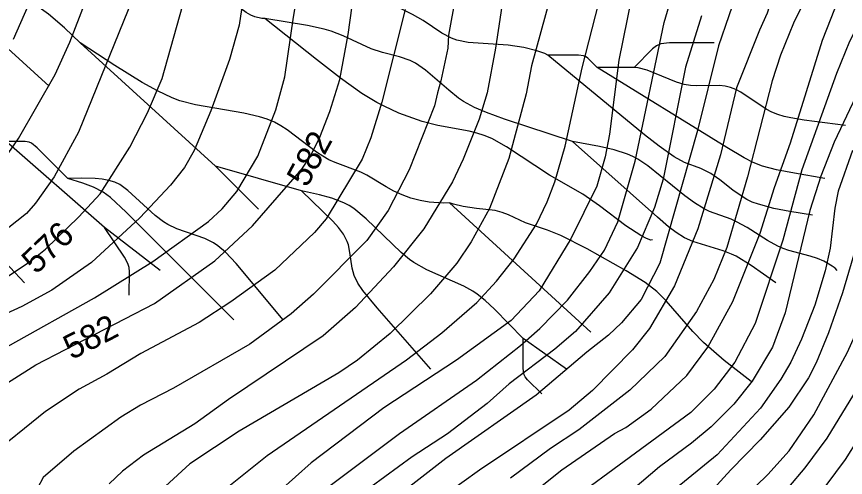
# Model space of a CAD drawing. Extents: x -709584 to -702006, y -1161789 to -1157496.
# Drawn here: x -708712.7 to -708376.2, y -1160078.5 to -1159891.3 of the extents above; entities that cross this region are included whole.
import ezdxf

# ---------------------------------------------------------------- set-up
doc = ezdxf.new("R2010")
doc.units = 0
for name, color, linetype in [('120_vrstevnice hlavní', 7, 'Continuous'), ('121_vrstevnice hlavní_popis', 7, 'Continuous'), ('122_vrstevnice základní', 7, 'Continuous'), ('411_akumulovaný odtok', 7, 'Continuous')]:
    doc.layers.add(name, color=color, linetype=linetype)

msp = doc.modelspace()

# ---------------------------------------------------------------- linework, layer by layer
at = {"layer": '120_vrstevnice hlavní'}
for points in [[(-708305.17, -1159622.86), (-708310.23, -1159641.37), (-708312.11, -1159650.63), (-708314.72, -1159669.14), (-708317.03, -1159706.17), (-708317.9, -1159757.09), (-708321.37, -1159808), (-708323.54, -1159821.89), (-708331.06, -1159840.4), (-708354.49, -1159891.32), (-708372, -1159923.72), (-708380.68, -1159942.23), (-708386.17, -1159956.12), (-708390.66, -1159970), (-708400.64, -1160011.66), (-708405.84, -1160025.55), (-708414.09, -1160039.43), (-708421.46, -1160048.69), (-708430.72, -1160057.95), (-708438.68, -1160064.6), (-708451.7, -1160074.15), (-708470.93, -1160090.64)], [(-708633.37, -1159627.34), (-708641.04, -1159641.37), (-708644.65, -1159650.05), (-708649.43, -1159676.09), (-708650.29, -1159684.77), (-708650.58, -1159697.78), (-708648.85, -1159734.52), (-708649.28, -1159755.35), (-708653.04, -1159775.89), (-708657.67, -1159792.09), (-708665.62, -1159808.29), (-708674.88, -1159824.49), (-708692.24, -1159852.84), (-708704.68, -1159878.88), (-708714.08, -1159900.57)], [(-708789.58, -1160084.27), (-708792.86, -1160072.53), (-708792.61, -1160069.11), (-708790.09, -1160064.95), (-708785.55, -1160060.3), (-708777.48, -1160053.94), (-708769.62, -1160049.56), (-708716.4, -1160025.26), (-708681.1, -1160005.59), (-708657.38, -1159990.83), (-708634.82, -1159974.49), (-708629.32, -1159969.43), (-708623.24, -1159962.34), (-708614.71, -1159948.02), (-708607.48, -1159929.21), (-708603.86, -1159915.76), (-708600.33, -1159891.54), (-708591.57, -1159840.69)], [(-708494.22, -1159876.56), (-708503.62, -1159911.28), (-708505.79, -1159922.71), (-708512.85, -1159948.88), (-708520.67, -1159969.19), (-708528.21, -1159982.73), (-708534, -1159991.41), (-708544.7, -1160003.85), (-708561.05, -1160020.05), (-708574.35, -1160030.9), (-708581.88, -1160035.96), (-708622.38, -1160059.68), (-708642.34, -1160072.99), (-708652.32, -1160082.1)], [(-708419.3, -1159878.59), (-708427.68, -1159903.18), (-708436.22, -1159937.6), (-708451.55, -1159991.41), (-708459.07, -1160006.17), (-708467.17, -1160015.71), (-708472.38, -1160020.77), (-708481.2, -1160027.57), (-708501.77, -1160045.09), (-708538.48, -1160070.82), (-708559.17, -1160086.88)], [(-708360.43, -1160046.09), (-708376.34, -1160071.26), (-708396.3, -1160098.16)]]:
    msp.add_lwpolyline(points, dxfattribs=at)
at = {"layer": '122_vrstevnice základní'}
for points in [[(-708524.02, -1160101.49), (-708491.33, -1160075.45), (-708469.92, -1160060.7), (-708465.29, -1160058.24), (-708455.02, -1160050.72), (-708440.56, -1160037.12), (-708432.02, -1160025.55), (-708421.9, -1160007.03), (-708410.76, -1159979.26), (-708404.98, -1159960.75), (-708398.47, -1159942.52), (-708385.45, -1159900.86), (-708373.73, -1159870.78), (-708363.9, -1159852.26), (-708354.35, -1159829.12), (-708349.87, -1159812.92), (-708345.96, -1159782.83), (-708346.1, -1159755.06), (-708350.16, -1159704.15), (-708349.58, -1159685.63), (-708347.7, -1159671.75), (-708342.63, -1159646.58), (-708332.22, -1159607.24)], [(-708437.52, -1160106.26), (-708407.72, -1160077.33), (-708399.05, -1160067.64), (-708389.07, -1160053.03), (-708375.32, -1160027.57), (-708371.13, -1160018.31), (-708364.76, -1159999.8), (-708358.26, -1159972.03), (-708355.51, -1159964.8), (-708350.59, -1159954.53), (-708323.11, -1159912.15), (-708298.81, -1159877.43), (-708289.69, -1159861.23), (-708285.64, -1159849.66), (-708281.45, -1159831.15), (-708279.71, -1159817.26), (-708279.86, -1159801.06), (-708278.12, -1159775.6), (-708277.25, -1159752.46), (-708274.07, -1159713.11), (-708273.93, -1159683.03), (-708272.48, -1159656.99), (-708271.04, -1159647.74), (-708260.77, -1159608.39)], [(-708317.9, -1159614.47), (-708327.01, -1159650.92), (-708332.22, -1159676.95), (-708333.67, -1159697.78), (-708333.52, -1159716.01), (-708332.08, -1159752.46), (-708334.24, -1159801.93), (-708336.7, -1159816.39), (-708343.21, -1159839.53), (-708347.41, -1159851.11), (-708358.98, -1159872.8), (-708363.9, -1159883.22), (-708370.55, -1159893.63), (-708374.46, -1159901.44), (-708379.81, -1159914.46), (-708393.84, -1159953.51), (-708401.65, -1159982.15), (-708412.79, -1160016), (-708421.03, -1160031.62), (-708429.42, -1160042.61), (-708438.97, -1160052.16), (-708513.03, -1160106.55)], [(-708585.93, -1160082.25), (-708557.29, -1160060.7), (-708526.04, -1160039), (-708508.11, -1160024.97), (-708500.3, -1160018.03), (-708489.01, -1160006.45), (-708479.9, -1159994.88), (-708473.97, -1159986.2), (-708468.62, -1159974.63), (-708461.53, -1159950.04), (-708449.82, -1159893.63), (-708436.22, -1159847.34), (-708433.47, -1159835.77), (-708430.43, -1159814.95), (-708430.87, -1159796.43), (-708432.17, -1159775.6), (-708434.48, -1159754.77), (-708437.52, -1159736.26), (-708439.26, -1159699.23), (-708437.52, -1159685.34), (-708434.48, -1159673.77), (-708426.53, -1159653.23), (-708413.08, -1159623.15)], [(-708252.23, -1159627.49), (-708256.43, -1159639.64), (-708259.32, -1159650.05), (-708261.63, -1159667.41), (-708261.63, -1159712.54), (-708265.25, -1159769.24), (-708266.55, -1159817.26), (-708269.01, -1159834.62), (-708271.76, -1159846.19), (-708275.08, -1159856.31), (-708279.28, -1159865.86), (-708307.34, -1159915.91), (-708316.74, -1159930.95), (-708335.84, -1159959.01), (-708345.24, -1159975.5), (-708351.6, -1159991.12), (-708362.31, -1160024.1), (-708366.93, -1160035.09), (-708383.71, -1160062.58), (-708392.68, -1160074.58), (-708419.15, -1160105.97)], [(-708724.06, -1160001.82), (-708707.14, -1159990.69), (-708701.06, -1159985.77), (-708687.47, -1159972.61), (-708678.79, -1159963.35), (-708666.78, -1159944.26), (-708659.55, -1159930.37), (-708653.62, -1159916.49), (-708638, -1159860.94), (-708632.79, -1159844.74), (-708618.91, -1159810.03), (-708614.85, -1159798.46), (-708610.8, -1159784.57), (-708607.33, -1159766.05), (-708607.48, -1159726.71), (-708609.07, -1159712.83), (-708613.55, -1159687.37), (-708614.71, -1159673.48), (-708613.99, -1159664.23), (-708612.69, -1159657.28), (-708608.64, -1159648.03), (-708603.28, -1159641.08), (-708594.75, -1159633.13)], [(-708627.29, -1160082.54), (-708610.95, -1160069.66), (-708554.39, -1160030.75), (-708540.07, -1160019.76), (-708525.9, -1160007.47), (-708517.8, -1159998.79), (-708510.71, -1159989.68), (-708501.6, -1159975.65), (-708497.26, -1159966.53), (-708494.22, -1159958.43), (-708490.03, -1159943.97), (-708483.08, -1159912.15), (-708474.98, -1159880.32), (-708465.44, -1159835.48), (-708464.42, -1159817.26), (-708465.44, -1159799.03), (-708478.17, -1159732.21), (-708481.49, -1159708.05), (-708480.91, -1159696.05), (-708479.47, -1159689.1), (-708473.54, -1159672.9), (-708466.31, -1159659.31), (-708461.82, -1159652.36), (-708446.2, -1159633.27)], [(-708356.81, -1159637.9), (-708361.87, -1159658.73), (-708364.19, -1159676.95), (-708364.04, -1159708.2), (-708362.74, -1159721.22), (-708359.7, -1159768.08), (-708360.43, -1159784.86), (-708364.33, -1159808), (-708367.08, -1159819.57), (-708371.42, -1159834.04), (-708381.98, -1159862.68), (-708397.31, -1159893.92), (-708402.52, -1159906.94), (-708405.99, -1159917.35), (-708415.97, -1159956.41), (-708424.36, -1159985.05), (-708429.57, -1159998.06), (-708436.65, -1160011.08), (-708449.53, -1160029.31), (-708463.7, -1160043.05), (-708484.39, -1160059.11), (-708495.96, -1160066.77), (-708512.16, -1160078.78)], [(-708613.26, -1159638.91), (-708618.04, -1159645.86), (-708622.38, -1159654.39), (-708624.55, -1159660.47), (-708626.57, -1159668.56), (-708627.01, -1159676.67), (-708626.14, -1159690.84), (-708619.77, -1159733.36), (-708619.48, -1159747.54), (-708621.65, -1159769.82), (-708623.24, -1159779.94), (-708624.83, -1159786.02), (-708633.08, -1159808.29), (-708643.93, -1159832.3), (-708654.92, -1159859.5), (-708663.89, -1159879.75), (-708687.61, -1159938.18), (-708697.45, -1159956.41), (-708705.11, -1159967.11), (-708708.73, -1159971.3), (-708721.31, -1159981.14)], [(-708718.57, -1159950.48), (-708711.91, -1159940.79), (-708697.01, -1159914.75), (-708691.08, -1159901.73), (-708671.7, -1159851.4), (-708665.05, -1159837.51), (-708650, -1159813.21), (-708645.23, -1159801.06), (-708640.89, -1159787.17), (-708634.82, -1159762.87), (-708632.5, -1159745.52), (-708632.07, -1159734.38), (-708633.66, -1159714.27), (-708636.26, -1159693.44), (-708636.55, -1159679.56), (-708635.1, -1159666.25), (-708631.92, -1159652.36), (-708625.99, -1159638.48)], [(-708375.76, -1159788.04), (-708379.08, -1159808.87), (-708387.76, -1159841.27), (-708392.39, -1159852.84), (-708396.01, -1159859.78), (-708401.5, -1159873.67), (-708405.71, -1159882.42), (-708408.01, -1159889.87), (-708411.05, -1159896.81), (-708420.41, -1159920.28), (-708426.96, -1159947.44), (-708436.07, -1159977.53), (-708445.62, -1160000.67), (-708455.75, -1160018.03), (-708462.69, -1160026.7), (-708478.89, -1160043.19), (-708488.29, -1160051.15), (-708524.71, -1160075.55), (-708539.08, -1160085.83)], [(-708528.79, -1159851.97), (-708537.33, -1159898.84), (-708537.62, -1159904.05), (-708540.4, -1159917.42), (-708541.81, -1159922.27), (-708543.05, -1159927.58), (-708553.38, -1159953.51), (-708561.92, -1159970), (-708570.45, -1159982.3), (-708592.15, -1160004), (-708601.26, -1160012.09), (-708618.04, -1160024.39), (-708648.99, -1160042.18), (-708662.44, -1160049.12), (-708670.4, -1160054.04), (-708689.49, -1160067.78), (-708701.93, -1160078.49), (-708704.25, -1160082.83)], [(-708616.59, -1159855.45), (-708622.38, -1159894.79), (-708626.28, -1159908.68), (-708633.8, -1159929.5), (-708640.6, -1159945.7), (-708644.51, -1159952.65), (-708650.29, -1159959.73), (-708662.73, -1159973.04), (-708682.26, -1159991.12), (-708698.46, -1160002.4), (-708710.61, -1160009.06), (-708740.98, -1160022.94)], [(-708723.63, -1160044.5), (-708704.97, -1160032.78), (-708656.8, -1160007.9), (-708632.21, -1159990.54), (-708616.88, -1159976.22), (-708596.92, -1159953.23), (-708593.45, -1159948.02), (-708589.54, -1159940.21), (-708585.49, -1159929.79), (-708581.44, -1159916.78), (-708578.12, -1159898.55), (-708574.79, -1159875.12)], [(-708514.62, -1159879.75), (-708518.23, -1159904.05), (-708521.7, -1159922.27), (-708524.89, -1159932.98), (-708531.4, -1159949.18), (-708535.73, -1159958.43), (-708547.31, -1159977.53), (-708559.75, -1159993), (-708575.08, -1160009.49), (-708588.24, -1160020.92), (-708626.72, -1160046.81), (-708640.31, -1160056.79), (-708661.14, -1160069.52), (-708669.68, -1160076.03), (-708675.17, -1160081.09)], [(-708462.98, -1159883.51), (-708468.19, -1159908.96), (-708471.95, -1159939.05), (-708473.68, -1159948.31), (-708477.15, -1159960.17), (-708487.71, -1159981.57), (-708500.58, -1160002.69), (-708511.87, -1160014.7), (-708534.08, -1160030.87), (-708563.65, -1160050.28), (-708593.16, -1160072.56), (-708605.89, -1160083.98)], [(-708554.97, -1159888.42), (-708564.37, -1159926.03), (-708568.86, -1159940.5), (-708572.47, -1159949.18), (-708587.08, -1159973.48), (-708591.71, -1159978.97), (-708607.91, -1159994.3), (-708625.7, -1160007.18), (-708638.58, -1160015.57), (-708662.3, -1160028.15), (-708676.04, -1160036.54), (-708687.32, -1160042.61), (-708701.06, -1160051.73), (-708724.5, -1160070.68)], [(-708434.63, -1159891.03), (-708441.14, -1159911.86), (-708450.25, -1159957.28), (-708453.72, -1159968.85), (-708460.66, -1159985.05), (-708472.09, -1160003.56), (-708485.83, -1160019.18), (-708494.22, -1160026.42), (-708512.74, -1160040.45), (-708521.7, -1160048.54), (-708537.76, -1160060.84), (-708552.08, -1160070.1), (-708574.35, -1160086.44)], [(-708373.3, -1159945.7), (-708379.08, -1159962.19), (-708380.53, -1159969.14), (-708382.41, -1159985.34), (-708384.44, -1159994.59), (-708388.63, -1160008.48), (-708393.98, -1160022.36), (-708398.32, -1160031.62), (-708402.37, -1160038.56), (-708410.62, -1160050.43), (-708428.26, -1160069.37), (-708463.56, -1160098.16)], [(-708367.22, -1159969.14), (-708377.35, -1160003.56), (-708382.99, -1160019.76), (-708388.05, -1160031.91), (-708391.23, -1160037.99), (-708399.19, -1160049.99), (-708410.76, -1160063.3), (-708422.77, -1160075.45), (-708439.69, -1160093.96)]]:
    msp.add_lwpolyline(points, dxfattribs=at)
at = {"layer": '411_akumulovaný odtok'}
for p, q in [((-708631.99, -1159952), (-708686.99, -1159902)), ((-708461.99, -1159912), (-708476.99, -1159912)), ((-708676.99, -1159977), (-708716.99, -1159942)), ((-708596.99, -1159962), (-708631.99, -1159952)), ((-708614.49, -1159969.5), (-708631.99, -1159952)), ((-708479.49, -1160019.5), (-708536.99, -1159967)), ((-708654.49, -1159994.5), (-708676.99, -1159977)), ((-708489.49, -1160034.5), (-708506.99, -1160022))]:
    msp.add_line(p, q, dxfattribs=at)
for points in [[(-708686.99, -1159902), (-708693.27, -1159895.87), (-708699.81, -1159890.33), (-708703.52, -1159887.55), (-708711.06, -1159882.53), (-708720.77, -1159877.04), (-708761.43, -1159855.42), (-708767.53, -1159851.9), (-708773.43, -1159848.11), (-708778.93, -1159843.82), (-708784.04, -1159839.04), (-708791.34, -1159831.38), (-708805.6, -1159815.53), (-708811.58, -1159809.57), (-708814.93, -1159806.56), (-708818.34, -1159803.73), (-708821.69, -1159801.25), (-708824.84, -1159799.25), (-708827.66, -1159797.85), (-708829.83, -1159797.11), (-708831.34, -1159796.85), (-708831.99, -1159797)], [(-708611.99, -1159892), (-708613.22, -1159892.09), (-708615.93, -1159891.43), (-708617.59, -1159890.71), (-708619.55, -1159889.55), (-708621.53, -1159888.06), (-708631.02, -1159879.71), (-708634.58, -1159877.11), (-708640.28, -1159873.65), (-708646.7, -1159870.72), (-708662.71, -1159865.02), (-708667.19, -1159863.24), (-708671.49, -1159861.14), (-708673.52, -1159859.91), (-708677.39, -1159857.15), (-708682.98, -1159852.6), (-708711.99, -1159827)], [(-708699.49, -1159919.5), (-708737.8, -1159884.67), (-708743.95, -1159879.45), (-708748.17, -1159876.28), (-708750.34, -1159874.87), (-708754.71, -1159872.68), (-708761.15, -1159870.03), (-708764.99, -1159867.84), (-708772.58, -1159862.9), (-708774.84, -1159861.63), (-708779.56, -1159859.36), (-708789.76, -1159855.21), (-708811.99, -1159847)], [(-708496.99, -1159907), (-708498.2, -1159906.33), (-708501.54, -1159905.12), (-708506.7, -1159903.86), (-708513.06, -1159902.95), (-708529.34, -1159901.74), (-708533.96, -1159900.81), (-708536.15, -1159900.06), (-708540.04, -1159897.99), (-708547.59, -1159892.92), (-708551.91, -1159890.43), (-708558.69, -1159887.08), (-708567.97, -1159883), (-708575.02, -1159880.24), (-708579.78, -1159878.68), (-708584.58, -1159877.56), (-708594.13, -1159875.9), (-708596.51, -1159875.22), (-708599.11, -1159874.13), (-708601.83, -1159872.7), (-708607.3, -1159869.25), (-708612.15, -1159865.76), (-708616.99, -1159862)], [(-708486.99, -1159942), (-708514.61, -1159933.01), (-708521.99, -1159930.3), (-708526.75, -1159928.24), (-708531.26, -1159925.77), (-708533.32, -1159924.35), (-708537.25, -1159921.2), (-708546.76, -1159912.99), (-708550.75, -1159910.21), (-708552.86, -1159909.1), (-708557.25, -1159907.57), (-708564.13, -1159905.87), (-708568.73, -1159904.36), (-708580.07, -1159899.07), (-708584.94, -1159897.21), (-708587.82, -1159896.39), (-708594.64, -1159894.88), (-708611.99, -1159892)], [(-708454.49, -1159982), (-708455.23, -1159982.09), (-708456.97, -1159981.5), (-708459.3, -1159980.28), (-708465.34, -1159976.23), (-708475.99, -1159968.18), (-708482.78, -1159963.36), (-708496.29, -1159955.64), (-708513.78, -1159944.13), (-708519.76, -1159940.85), (-708522.87, -1159939.55), (-708525.89, -1159938.62), (-708528.99, -1159937.89), (-708541.71, -1159935.54), (-708548.09, -1159933.83), (-708557.46, -1159930.45), (-708563.52, -1159927.73), (-708566.47, -1159926.19), (-708572.48, -1159922.51), (-708581.15, -1159916.33), (-708590.91, -1159908.76), (-708611.99, -1159892)], [(-708536.99, -1159967), (-708539.36, -1159967.1), (-708545.17, -1159966.64), (-708548.81, -1159966.01), (-708552.65, -1159965.01), (-708556.14, -1159963.72), (-708559.5, -1159962.16), (-708562.66, -1159960.46), (-708570.48, -1159955.73), (-708572.98, -1159954.45), (-708583.36, -1159950.57), (-708585.89, -1159949.43), (-708588.44, -1159948), (-708590.9, -1159946.36), (-708602.91, -1159937.26), (-708605.43, -1159935.64), (-708608.04, -1159934.23), (-708610.98, -1159933.01), (-708614.04, -1159932.03), (-708620.4, -1159930.57), (-708640.04, -1159927.18), (-708646.41, -1159925.48), (-708649.5, -1159924.33), (-708655.48, -1159921.5), (-708661.68, -1159918.03), (-708672.83, -1159911.11), (-708686.99, -1159902)], [(-708429.49, -1159902), (-708447.66, -1159901.93), (-708451.15, -1159902.28), (-708452.94, -1159903.13), (-708454.52, -1159904.42), (-708461.99, -1159912)], [(-708476.99, -1159912), (-708480.8, -1159908.15), (-708481.76, -1159907.46), (-708482.5, -1159907.17), (-708484.62, -1159906.97), (-708496.99, -1159907)], [(-708389.49, -1159972), (-708398.79, -1159970.47), (-708405.25, -1159969.18), (-708411.44, -1159967.55), (-708414.03, -1159966.61), (-708416.23, -1159965.55), (-708418.16, -1159964.4), (-708421.84, -1159961.74), (-708427.2, -1159957.55), (-708430.89, -1159955.03), (-708434.94, -1159953.04), (-708441.47, -1159950.5), (-708445.7, -1159948.19), (-708451.78, -1159943.92), (-708457.73, -1159939.25), (-708496.99, -1159907)], [(-708709.49, -1159999.5), (-708767.85, -1159937.19), (-708774.11, -1159930.32), (-708777.38, -1159925.86), (-708778.87, -1159923.38), (-708780.14, -1159920.86), (-708781.08, -1159918.41), (-708781.62, -1159916.42), (-708782.06, -1159913.29), (-708781.99, -1159912)], [(-708384.49, -1159957), (-708396.8, -1159954.93), (-708404.13, -1159953.53), (-708409.89, -1159952), (-708413.6, -1159950.54), (-708417.23, -1159948.69), (-708424.32, -1159944.52), (-708476.99, -1159912)], [(-708376.1, -1159935.52), (-708392.89, -1159933.41), (-708398.36, -1159932.45), (-708401.03, -1159931.81), (-708403.61, -1159931.03), (-708406.1, -1159930.04), (-708408.31, -1159928.88), (-708418.63, -1159922), (-708420.72, -1159920.88), (-708422.89, -1159920.02), (-708425.07, -1159919.53), (-708427.33, -1159919.3), (-708436.66, -1159919.43), (-708439.06, -1159919.31), (-708441.71, -1159918.86), (-708444.77, -1159917.92), (-708456.63, -1159913.02), (-708460.4, -1159912.05), (-708461.53, -1159911.92), (-708461.99, -1159912)], [(-708691.99, -1159957), (-708704.32, -1159944.6), (-708706.64, -1159942.68), (-708707.67, -1159942.23), (-708709.32, -1159941.96), (-708716.99, -1159942)], [(-708379.49, -1159994.5), (-708380.39, -1159993.51), (-708381.54, -1159992.64), (-708384.96, -1159990.65), (-708387.56, -1159989.56), (-708390.43, -1159988.61), (-708399.11, -1159986.26), (-708401.48, -1159985.49), (-708403.67, -1159984.54), (-708407.88, -1159982.19), (-708416.14, -1159976.95), (-708420.35, -1159974.6), (-708422.52, -1159973.61), (-708431.42, -1159970.45), (-708433.49, -1159969.42), (-708437.47, -1159966.93), (-708441.32, -1159964.09), (-708456.47, -1159951.95), (-708460.44, -1159949.26), (-708462.51, -1159948.11), (-708464.68, -1159947.15), (-708470.05, -1159945.45), (-708475.98, -1159944.06), (-708486.99, -1159942)], [(-708404.49, -1159999.5), (-708414.41, -1159992.43), (-708420.6, -1159988.65), (-708422.37, -1159987.81), (-708425.82, -1159986.5), (-708438.2, -1159982.61), (-708441.53, -1159981.13), (-708444.84, -1159979.06), (-708447.99, -1159976.66), (-708452.55, -1159972.79), (-708486.99, -1159942)], [(-708604.49, -1160014.5), (-708623.63, -1159991.59), (-708627.96, -1159987.04), (-708631.07, -1159984.38), (-708632.75, -1159983.24), (-708636.29, -1159981.5), (-708647.68, -1159977.46), (-708651.29, -1159975.77), (-708653.07, -1159974.66), (-708656.44, -1159972.09), (-708667.55, -1159961.99), (-708670.88, -1159959.54), (-708672.86, -1159958.56), (-708675.29, -1159957.82), (-708678, -1159957.33), (-708680.83, -1159957.03), (-708686.25, -1159956.86), (-708691.99, -1159957)], [(-708624.49, -1160014.5), (-708668.2, -1159970.7), (-708674.62, -1159964.71), (-708677.61, -1159962.57), (-708681.57, -1159960.62), (-708685.8, -1159958.99), (-708691.99, -1159957)], [(-708506.99, -1160022), (-708518.64, -1160010.17), (-708522.4, -1160006.68), (-708525.75, -1160003.99), (-708527.5, -1160002.79), (-708531.06, -1160000.81), (-708546.11, -1159994.14), (-708551.46, -1159991.2), (-708553.23, -1159989.95), (-708556.59, -1159987.17), (-708570.81, -1159973.38), (-708575.78, -1159969.19), (-708577.67, -1159967.98), (-708579.8, -1159966.93), (-708584.74, -1159965.11), (-708589.8, -1159963.67), (-708596.99, -1159962)], [(-708544.49, -1160034.5), (-708566.31, -1160009.56), (-708572.11, -1160002.53), (-708574.11, -1159999.6), (-708575.66, -1159996.5), (-708576.47, -1159993.47), (-708577.36, -1159987.15), (-708577.97, -1159984.07), (-708578.45, -1159982.6), (-708579.99, -1159979.7), (-708582.01, -1159977.01), (-708584.34, -1159974.4), (-708596.99, -1159962)], [(-708414.49, -1160039.5), (-708425.36, -1160030.95), (-708433.78, -1160023.65), (-708438.12, -1160019.22), (-708448.9, -1160006.7), (-708452.82, -1160002.91), (-708457.54, -1159999.31), (-708465.18, -1159994.51), (-708481.05, -1159985.67), (-708491.79, -1159980.26), (-708497.22, -1159978.01), (-708506.1, -1159975.03), (-708513, -1159971.83), (-708515.6, -1159970.83), (-708518.45, -1159970.07), (-708526.04, -1159969.22), (-708531.38, -1159968.42), (-708535.37, -1159967.55), (-708536.99, -1159967)], [(-708666.99, -1160004.5), (-708666.93, -1159994.96), (-708667.07, -1159993.22), (-708667.5, -1159991.56), (-708668.94, -1159988.99), (-708676.99, -1159977)], [(-708499.49, -1160044.5), (-708505.26, -1160038.81), (-708506.19, -1160037.68), (-708506.64, -1160036.86), (-708506.96, -1160035.49), (-708507.04, -1160034.03), (-708506.99, -1160022)]]:
    msp.add_lwpolyline(points, dxfattribs=at)

# ---------------------------------------------------------------- texts
at = {"layer": '121_vrstevnice hlavní_popis'}
for s, rotation, p in [('582', 61.6043, (-708594.81, -1159961.08)), ('576', 43.7209, (-708704.81, -1159996.32)), ('582', 27.008, (-708690.44, -1160030.89))]:
    msp.add_text(s, height=10, rotation=rotation, dxfattribs=at).set_placement(p)

doc.saveas('drawing.dxf')
